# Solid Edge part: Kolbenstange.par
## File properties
Username: bmolnar
Dokumentum tartalom típus: 0
Author: bmolnar
Last saved by: bmolnar
Revision: 80
Sűrűség: 0,000 kg/m^3
Pontosság: 0,990
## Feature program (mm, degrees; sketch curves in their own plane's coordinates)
base feature "unnamed BaseFeature 1"
sketch for "unnamed Protrusion 1" plane through (0, 0, -11.1) normal (0, 0, -1) x-axis (1, 0, 0)
  circle centre (0, 0) radius 16
extrude "unnamed Protrusion 1" add finite 15.8 along +normal
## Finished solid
Body 1: solid body, 13 faces, 19 edges, 8 vertices.
  Faces by surface: plane 7, cylinder 3, cone 2, torus 1
  Edges by curve: circle 9, line 6, ellipse 2, intersection 2
Bounding box of the edges (mm; curved faces can reach further): 32.000 x 32.000 x 56.414, from (-16, -16, -26.9) to (16, 16, 29.5137).
Cylindrical faces by radius (mm): R3.3235 x1, R6 x1, R16 x1
Conical faces (half-angle, radius in mm at the cone's reference point): 45 deg R3.6735 x1, 59 deg R1.6618 x1
Toroidal faces (ring radius, tube radius in mm): R4.8 r1.2 x1
Planar faces by outward normal: +x 1, +z 2, -x 1, -z 1, oblique 2
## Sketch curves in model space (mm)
circle centre (0, 0, -11.1) radius 16
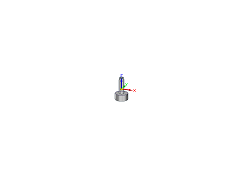
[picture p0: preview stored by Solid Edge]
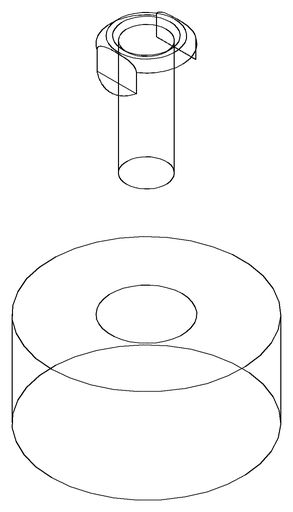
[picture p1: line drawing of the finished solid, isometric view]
